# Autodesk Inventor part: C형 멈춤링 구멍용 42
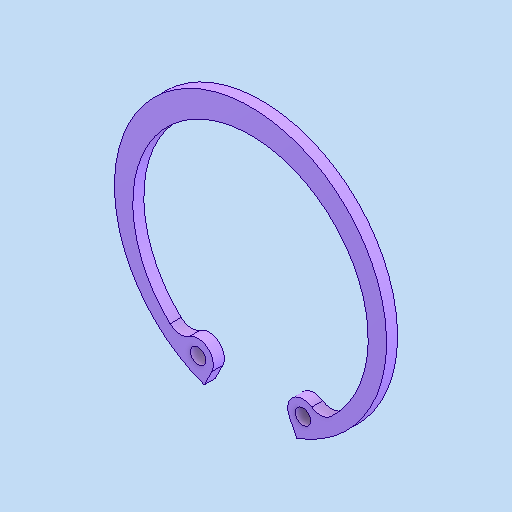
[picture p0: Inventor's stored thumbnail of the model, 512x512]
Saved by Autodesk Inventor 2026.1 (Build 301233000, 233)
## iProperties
Created: 2025-11
Part Number: C형 멈춤링 구멍용 42
Material: 강철, 연강
Description: 리테이닝 링(C형)
Document SubType Name: Modeling
Designer: PC-30
Density: 7.85 g/cm^3
Appearance: 기본값
Author: jhkim
Sending System: Autodesk Inventor 2026
Preprocessor: ST-DEVELOPER v20.1
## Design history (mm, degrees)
feature "Solid1"
node "솔리드1"
